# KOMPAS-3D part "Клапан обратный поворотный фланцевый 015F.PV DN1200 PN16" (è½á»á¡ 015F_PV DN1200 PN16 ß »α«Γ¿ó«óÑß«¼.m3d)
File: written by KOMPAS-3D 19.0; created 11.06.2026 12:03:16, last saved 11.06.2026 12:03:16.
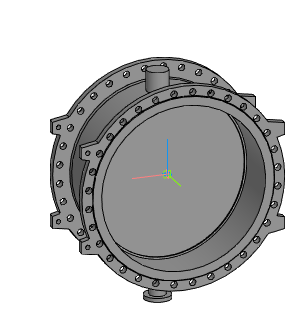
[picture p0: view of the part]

Document properties: Автор: Энергия; Полное имя файла: Z:\3.Личные\kachalov\001_3d для проектировщиков\5.5 Тип 015F.PV Клапан обратный поворотный с двумя эксцентриками\_stp_Клапан 015F.PV DN300-DN1200 с противовесом\Клапан 015F_PV DN1200 PN16 с противовесом.m3d

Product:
- Part/product: Клапан обратный поворотный фланцевый 015F.PV DN1200 PN16

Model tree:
1. Операция без истории:1
2. Сплайн:1
     Координата Y = 30; Координата Z = 600; Вес = 1; Координата X = 1200; Координата Y = 187.983; Координата Z = 600; Вес = 0.333333; Координата X = 1200; Координата Y = 187.983; Координата Z = -600; Вес = 0.333333; Координата Y = 30; Координата Z = -600; Вес = 1; Координата X = -1200; Координата Y = -127.983; Координата Z = -600; Вес = 0.333333; Координата X = -1200; Координата Y = -127.983; Координата Z = 600; Вес = 0.333333; Порядок = 4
